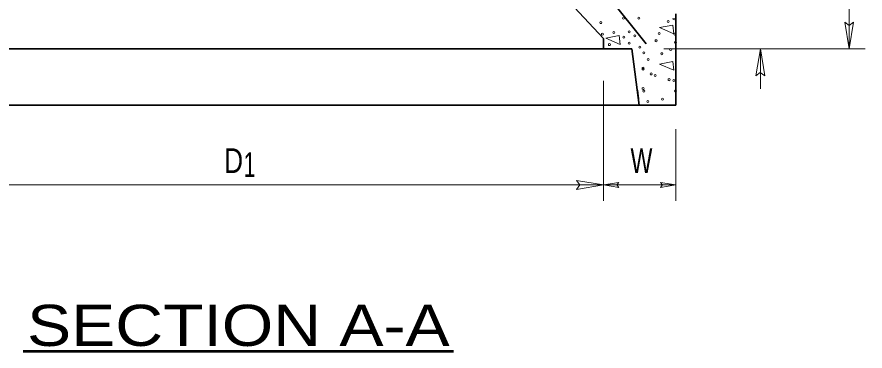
# Model space of a CAD drawing. Extents: x 5.1 to 20.2, y -16.7 to 4.3.
# Drawn here: x 11.185 to 15.609, y -6.022 to -4.277 of the extents above; entities that cross this region are included whole.
import ezdxf
from ezdxf.enums import TextEntityAlignment as Align

# ---------------------------------------------------------------- set-up
doc = ezdxf.new("R2010")
doc.units = 0
doc.header["$LTSCALE"] = 0.052
for name, color, linetype, lineweight in [('1', 7, 'Continuous', 35), ('10', 7, 'Continuous', 13), ('12', 7, 'Continuous', 53), ('13', 7, 'Continuous', 25), ('6', 7, 'Continuous', 13)]:
    doc.layers.add(name, color=color, linetype=linetype, lineweight=lineweight)

msp = doc.modelspace()

# ---------------------------------------------------------------- linework, layer by layer
at = {"layer": '1'}
for p, q in [((14.46767, -4.41642), (13.61783, -3.35658)), ((14.24408, -4.38925), (13.44808, -3.5325)), ((14.62242, -4.73767), (14.62242, -4.26)), ((14.24408, -4.38925), (14.24408, -4.44358)), ((10.265, -4.44358), (14.39283, -4.44358)), ((14.43067, -4.73767), (14.39283, -4.4435)), ((10.07242, -4.73767), (14.62242, -4.73767))]:
    msp.add_line(p, q, dxfattribs=at)
at = {"layer": '10'}
for p, q in [((15.52533, -2.96833), (15.52533, -4.44358)), ((15.50258, -4.3035), (15.52533, -4.44358)), ((15.50258, -4.3035), (15.52583, -4.32108)), ((15.54925, -4.30367), (15.52533, -4.44358)), ((15.54925, -4.30367), (15.52583, -4.32108)), ((14.55875, -4.44358), (15.60867, -4.44358)), ((15.03892, -4.5835), (15.06283, -4.44358)), ((15.08558, -4.58367), (15.06283, -4.44358)), ((15.06283, -4.44358), (15.06283, -4.65192)), ((15.03892, -4.5835), (15.06233, -4.56608)), ((15.08558, -4.58367), (15.06233, -4.56608)), ((14.24408, -4.61083), (14.24408, -5.23767)), ((14.62242, -4.86267), (14.62242, -5.23767)), ((14.10408, -5.131), (14.24408, -5.15433)), ((14.10408, -5.131), (14.12158, -5.15433)), ((14.10408, -5.17767), (14.24408, -5.15433)), ((14.10408, -5.17767), (14.12158, -5.15433)), ((14.32408, -5.141), (14.24408, -5.15433)), ((14.32408, -5.16767), (14.24408, -5.15433)), ((14.32408, -5.141), (14.31408, -5.15433)), ((14.32408, -5.16767), (14.31408, -5.15433)), ((14.54242, -5.141), (14.62242, -5.15433)), ((14.54242, -5.141), (14.55242, -5.15433)), ((14.54242, -5.16767), (14.62242, -5.15433)), ((14.54242, -5.16767), (14.55242, -5.15433))]:
    msp.add_line(p, q, dxfattribs=at)
msp.add_lwpolyline([(14.62242, -5.15433), (14.24408, -5.15433), (10.45017, -5.15433)], dxfattribs=at)
at = {"layer": '12'}
msp.add_line((11.2165, -6.02175), (13.46233, -6.02175), dxfattribs=at)
at = {"layer": '6'}
for p, q in [((14.60433, -4.287), (14.62383, -4.28317)), ((14.62375, -4.29533), (14.60433, -4.287)), ((14.616, -4.73742), (14.62242, -4.73617))]:
    msp.add_line(p, q, dxfattribs=at)
for points in [[(14.5365, -4.33258), (14.60542, -4.31908), (14.61142, -4.36467)], [(14.25658, -4.38775), (14.3255, -4.37425), (14.3315, -4.41983)], [(14.5365, -4.52342), (14.60542, -4.50992), (14.61142, -4.5555)]]:
    msp.add_lwpolyline(points, close=True, dxfattribs=at)
msp.add_lwpolyline([(14.42025, -4.65883), (14.423, -4.65833), (14.429, -4.70392), (14.426, -4.70258)], dxfattribs=at)
for centre in [(14.34867, -4.28292), (14.42925, -4.28292), (14.22992, -4.30646), (14.58192, -4.29992), (14.23842, -4.36675), (14.29775, -4.35825), (14.35101, -4.38191), (14.37833, -4.354), (14.40808, -4.37525), (14.53525, -4.3625), (14.61583, -4.36675), (14.27497, -4.4214), (14.37833, -4.41342), (14.51833, -4.40067), (14.62008, -4.40917), (14.4335, -4.43458), (14.45467, -4.46425), (14.548, -4.4685), (14.59467, -4.44733), (14.47742, -4.4995), (14.4505, -4.54483), (14.4505, -4.54908), (14.49283, -4.57458), (14.51408, -4.583), (14.58617, -4.60425), (14.61158, -4.6085), (14.4505, -4.65092), (14.45467, -4.66358), (14.62008, -4.66358), (14.47592, -4.71875), (14.55225, -4.706)]:
    msp.add_circle(centre, 0.00525, dxfattribs=at)

# ---------------------------------------------------------------- texts
at = {"layer": '12', "width": 1.2}
msp.add_text('SECTION A-A', height=0.215, dxfattribs=at).set_placement((12.33942, -5.995), align=Align.CENTER)
at = {"layer": '13'}
for s, width, p in [('D', 0.8, (12.31442, -5.09183)), ('1', 0.65, (12.39779, -5.11267)), ('W', 0.7, (14.44233, -5.09183))]:
    msp.add_text(s, height=0.129, dxfattribs=dict(at, width=width)).set_placement(p, align=Align.CENTER)

doc.saveas('drawing.dxf')
